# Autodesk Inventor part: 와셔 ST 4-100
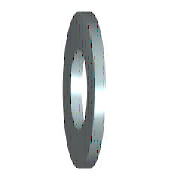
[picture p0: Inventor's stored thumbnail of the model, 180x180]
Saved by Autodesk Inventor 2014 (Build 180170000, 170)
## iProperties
IsCustomPart: 0
Created: 2012-02
Part Number: 와셔 ST 4-100
Material: 강철, 연강
Description: 평면 와셔 - 일반 시리즈 - 제품 등급 C
Document SubType Name: Modeling
Standard: ISO 7091
Designer: mduedu
Standard Revision: Second edition 2000-06-01
Standards Organization: ISO
Language: ko-KR
Size Designation: ST 4 - 100 HV
Categories: <MemberInstance><Categories><Category DisplayName="조임쇠" InternalName="e4da775c-781d-43d5-af7c-5136215cf5a6" Mnemonic="FSTN"><Category DisplayName="와셔" InternalN
Density: 7.86 g/cm^3
Mass: 0.492315 g
Surface Area: 1.70824 cm^2
Volume: 0.0626355 cm^3
Appearance: 파란색 - 벽 페인트 - 광택
Author: mduedu
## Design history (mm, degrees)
sketch "스케치"
  geometry: C1 r 5 at (0, 0); C2 r 2.25 at (0, 0); 1 further point
  constraints: 2 centre point, 2 coincident
  dimensions: "d0" = 4.5 diameter of C2 (= SD1); "d1" = 10 diameter of C1 (= SD2)
extrude "본체" new body sketch "스케치" distance "d2" = 1 (= SD); taper "d3" = 0 deg
workaxis "Work Axis1"
workplane "Work Plane1"
body "Solid1"
other parameters: "SD1" = 4.5 [user parameter; used in 1 equation term], "SD2" = 10 [user parameter; used in 1 equation term], "SD" = 1 [user parameter; used in 1 equation term], "d4" = 0, "d5" = 0, "d6" = 0, "d7" = 0, "NND" = 4 [user parameter]
